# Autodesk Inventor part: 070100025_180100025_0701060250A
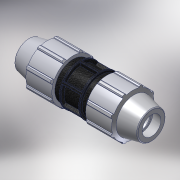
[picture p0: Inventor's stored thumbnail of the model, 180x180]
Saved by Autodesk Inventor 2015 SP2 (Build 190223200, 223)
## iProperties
Created: 2017-02
Part Number: 070100025_180100025_0701060250A
Material: PVC-Piping
Description: PLASSON COUPLER 25-25
Document SubType Name: Modeling
Designer: KIM
Mass: 92.6774 g
Surface Area: 199.44 cm^2
Volume: 66.1981 cm^3
Density: 1.4 g/cm^3
Appearance: PTFE
Author: KIM
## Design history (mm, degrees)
derived "07010.ipt"
feature "Solid1::07010.ipt"
tag "TaggingFeature1"
body "Solid1"
other parameters: "d1" = 126, "d2" = 25, "d4" = 10.5, "d5" = 18, "d7" = 54, "d8" = 40.5, "d9" = 18, "d11" = 1.8, "d12" = 43.2, "d13" = 120 deg, "d14" = 37.5, "d15" = 10 deg, "d16" = 48.6, "d18" = 1.25, "d19" = 35 deg, "d20" = 17.5 deg, "d21" = 50.22, "d23" = 0, "d25" = 360 deg, "d27" = 1.08, "d33" = 0.5, "d34" = 2.7, "d36" = 0, "d37" = 0.5, "d38" = 0.5, "d40" = 360 deg, "d42" = 27.72, "d43" = 1.62, "d46" = 0.75, "d49" = 61, "d_" = 25, "E_" = 54, "H_" = 126, "l_" = 61
